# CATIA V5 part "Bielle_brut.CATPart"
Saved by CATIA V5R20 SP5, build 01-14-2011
Part number: Bielle
Publications: "Longueur_bielle"
Bounding box of the stored display mesh (mm): x -65 to 5, y 0 to 5, z -5 to 5
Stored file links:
  G:\IAO\Bielle_brut.CATPart
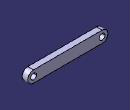
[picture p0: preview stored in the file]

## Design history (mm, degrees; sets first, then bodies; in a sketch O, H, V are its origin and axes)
Parameters
  Longueur_bielle = 60 mm
Body1 (main body)
  Sketch1 on zx-plane, origin (0, 0, 0), H (-1, 0, 0), V (0, 0, 1)
    arc A1 centre (0, 0) radius 5 from (0, 5) to (0, -5) ccw
    arc A2 centre (60, 0) radius 5 from (60, -5) to (60, 5) ccw
    point P1 (60, 0)
    line L1 (0, 5) -> (60, 5)
    point P2 (0, 5)
    line L2 (60, -5) -> (0, -5)
    circle A3 centre (60, 0) radius 2.5
    circle A4 centre (0, 0) radius 2.5
    radius A1 = 5
    radius A2 = 5
    distance P1 O = 60 {= Longueur_bielle}
    radius A3 = 2.5
    radius A4 = 2.5
    coincidence: P1 H, P2 V
    tangency: L1 A2, L2 A1, L2 A2
  Pad1: profile Sketch1, direction (0, 1, 0), length 5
